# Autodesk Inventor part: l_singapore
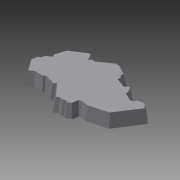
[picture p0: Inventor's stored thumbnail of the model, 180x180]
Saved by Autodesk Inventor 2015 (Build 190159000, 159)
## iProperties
Created: 2015-04
Part Number: l_singapore
Material: Generic
Document SubType Name: Modeling
Designer: User
Density: 1 g/cm^3
Appearance: Default
Author: User
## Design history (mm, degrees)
sketch "Sketch1"
  geometry: L1 (7.387, 20.778)-(12.792, 24.23); L2 (12.792, 24.23)-(13.54, 24.188); L3 (13.54, 24.188)-(14.746, 21.818); L4 (14.746, 21.818)-(15.536, 22.65); L5 (15.536, 22.65)-(16.784, 22.483); L6 (16.784, 22.483)-(20.36, 25.02); L7 (20.36, 25.02)-(21.815, 26.018); L8 (21.815, 26.018)-(23.187, 26.018); L9 (23.187, 26.018)-(27.054, 23.855); L10 (27.054, 23.855)-(26.763, 23.149); L11 (26.763, 23.149)-(27.761, 21.776); L12 (27.761, 21.776)-(27.511, 21.028); L13 (27.511, 21.028)-(31.42, 19.489); L14 (31.42, 19.489)-(32.501, 20.612); L15 (32.501, 20.612)-(33.041, 20.487); L16 (33.041, 20.487)-(34.289, 18.325); L17 (34.289, 18.325)-(34.164, 17.535); L18 (34.164, 17.535)-(34.871, 17.452); L19 (34.871, 17.452)-(37.407, 15.997); L20 (37.407, 15.997)-(38.696, 16.537); L21 (38.696, 16.537)-(38.946, 17.369); L22 (38.946, 17.369)-(41.399, 17.951); L23 (41.399, 17.951)-(43.187, 16.246); L24 (43.187, 16.246)-(37.657, 7.681); L25 (37.657, 7.681)-(30.63, 5.727); L26 (30.63, 5.727)-(28.093, 6.101); L27 (28.093, 6.101)-(27.012, 5.727); L28 (27.012, 5.727)-(26.638, 3.398); L29 (26.638, 3.398)-(25.432, 2.733); L30 (25.432, 2.733)-(24.559, 3.19); L31 (24.559, 3.19)-(23.686, 2.733); L32 (23.686, 2.733)-(22.189, 3.024); L33 (22.189, 3.024)-(21.233, 2.4); L34 (21.233, 2.4)-(16.742, 7.265); L35 (16.742, 7.265)-(15.869, 6.433); L36 (15.869, 6.433)-(14.663, 7.099); L37 (14.663, 7.099)-(13.291, 7.14); L38 (13.291, 7.14)-(12.917, 7.681); L39 (12.917, 7.681)-(11.794, 7.598); L40 (11.794, 7.598)-(11.42, 7.099); L41 (11.42, 7.099)-(8.177, 7.099); L42 (8.177, 7.099)-(6.389, 6.018); L43 (6.389, 6.018)-(3.187, 10.508); L44 (3.187, 10.508)-(3.686, 12.754); L45 (3.686, 12.754)-(4.268, 12.754); L46 (4.268, 12.754)-(4.85, 14.5); L47 (4.85, 14.5)-(6.721, 15.83); L48 (6.721, 15.83)-(6.056, 16.62); L49 (6.056, 16.62)-(7.387, 20.778)
  constraints: 98 end point, 3 parallel
extrude "Extrusion1" new body sketch "Sketch1" distance "d3" = 5; taper "d4" = 10 deg
body "Solid1"
